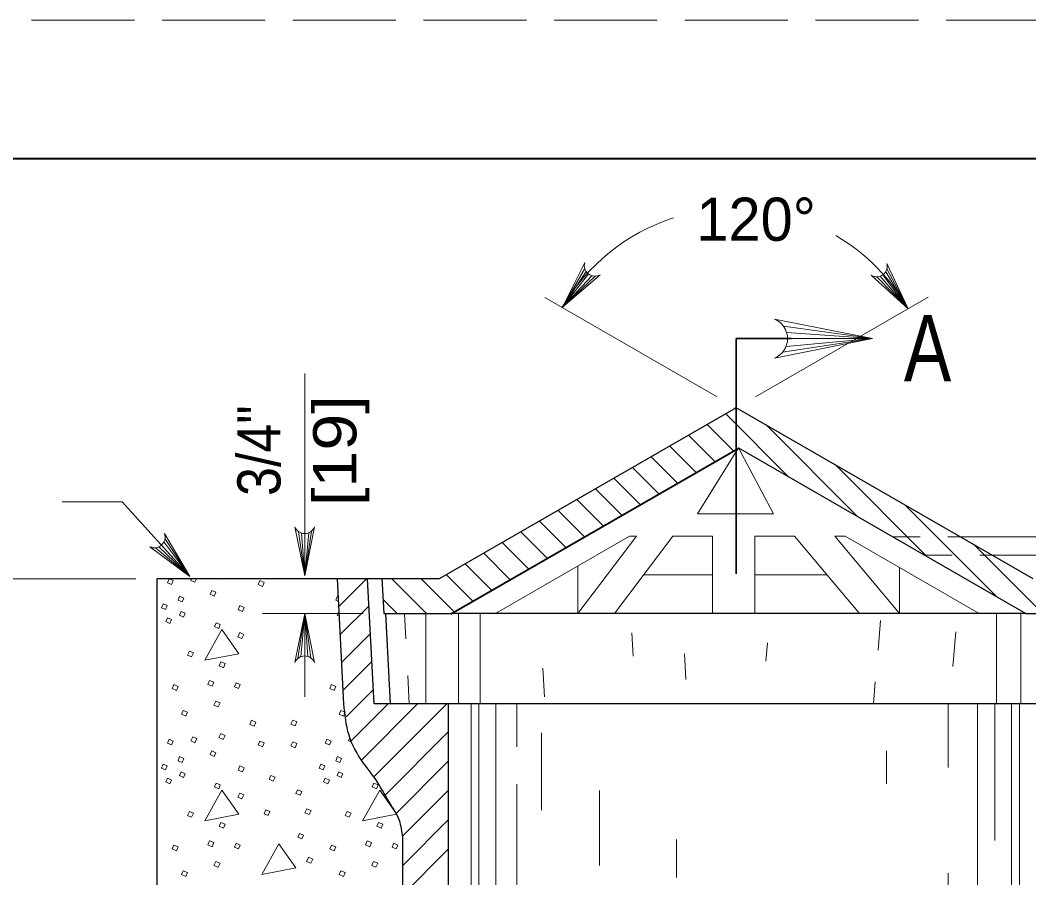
# Model space of a CAD drawing. Extents: x 1036.7 to 1070.7, y 883.9 to 905.9.
# Drawn here: x 1045.244 to 1048.888, y 902.809 to 905.908 of the extents above; entities that cross this region are included whole.
import ezdxf
from ezdxf.enums import TextEntityAlignment as Align

# ---------------------------------------------------------------- set-up
doc = ezdxf.new("R2010")
doc.units = 0
doc.header["$LTSCALE"] = 0.062
doc.linetypes.add('LONG_DASHED', pattern=[7.5, 6, -1.5])
doc.linetypes.add('SHORT_DASHED', pattern=[2.7, 1.5, -1.2])
doc.layers.add('1', color=7, linetype='Continuous', lineweight=13)

msp = doc.modelspace()

# ---------------------------------------------------------------- linework, layer by layer
at = {"layer": '1', "lineweight": 25}
for p, q in [((1038.67333, 905.40825), (1070.17333, 905.40825)), ((1047.83108, 904.5075), (1046.75733, 903.88892)), ((1048.90392, 903.88892), (1047.83108, 904.5075)), ((1046.8015, 903.7615), (1047.8405, 904.36)), ((1046.41367, 903.43767), (1046.38992, 903.88892)), ((1046.5505, 903.88892), (1046.38992, 903.88892)), ((1046.5505, 903.89158), (1046.55725, 903.76383)), ((1046.75733, 903.88892), (1046.5505, 903.88892)), ((1046.55733, 903.76383), (1046.80025, 903.76383)), ((1046.58208, 903.43767), (1046.56483, 903.76383)), ((1048.87742, 903.76383), (1046.80025, 903.76383)), ((1048.89925, 903.43767), (1046.7915, 903.43767)), ((1048.93683, 903.43767), (1046.7915, 903.43767)), ((1046.62592, 900.59025), (1046.62592, 902.95508))]:
    msp.add_line(p, q, dxfattribs=at)
at = {"layer": '1'}
for p, q in [((1047.28333, 905.01067), (1047.20258, 904.8705)), ((1048.37533, 905.01017), (1048.45192, 904.86517)), ((1047.28875, 904.99958), (1047.20258, 904.8705)), ((1047.29667, 904.99133), (1047.20258, 904.8705)), ((1047.30975, 904.98475), (1047.20258, 904.8705)), ((1047.32175, 904.98317), (1047.20258, 904.8705)), ((1048.3385, 904.98058), (1048.45192, 904.86517)), ((1048.35067, 904.98283), (1048.45192, 904.86517)), ((1048.36075, 904.98825), (1048.45192, 904.86517)), ((1048.37067, 904.99908), (1048.45192, 904.86517)), ((1047.76183, 904.54742), (1047.13992, 904.90608)), ((1048.52417, 904.90675), (1047.90033, 904.54742)), ((1048.00208, 904.80225), (1048.32258, 904.75742)), ((1047.99825, 904.70783), (1048.32258, 904.75742)), ((1048.01058, 904.72858), (1048.32258, 904.75742)), ((1048.01292, 904.78008), (1048.32258, 904.75742)), ((1048.01625, 904.75742), (1048.32258, 904.75742)), ((1046.27183, 904.63175), (1046.27183, 903.89992)), ((1047.83108, 904.5075), (1047.82567, 904.50742)), ((1047.79275, 904.4855), (1048.02, 904.25808)), ((1047.7255, 904.44667), (1047.82058, 904.35158)), ((1047.93867, 904.4455), (1048.2705, 904.11375)), ((1047.65817, 904.40792), (1047.75333, 904.31283)), ((1046.80025, 903.76383), (1047.83925, 904.36233)), ((1047.591, 904.36917), (1047.686, 904.27408)), ((1047.69058, 904.12417), (1047.83925, 904.36233)), ((1047.96542, 904.12417), (1047.83925, 904.36233)), ((1047.52367, 904.33042), (1047.61883, 904.23533)), ((1047.4565, 904.29167), (1047.5515, 904.19667)), ((1048.18908, 904.30108), (1048.521, 903.96933)), ((1047.38917, 904.25292), (1047.48425, 904.15783)), ((1047.32192, 904.21417), (1047.417, 904.11908)), ((1045.39583, 904.16733), (1045.613, 904.16733)), ((1045.85717, 903.8975), (1045.613, 904.16733)), ((1047.25467, 904.17542), (1047.34975, 904.08033)), ((1047.18742, 904.13667), (1047.2825, 904.04158)), ((1048.43958, 904.15667), (1048.77133, 903.82492)), ((1047.12008, 904.09792), (1047.21525, 904.00283)), ((1047.69058, 904.12417), (1047.96542, 904.12417)), ((1046.24942, 904.06017), (1046.27183, 903.89992)), ((1046.29667, 904.062), (1046.27183, 903.89992)), ((1047.05292, 904.05925), (1047.14792, 903.96408)), ((1045.76358, 904.02308), (1045.85717, 903.8975)), ((1045.76717, 904.03458), (1045.85717, 903.8975)), ((1046.2605, 904.05467), (1046.27183, 903.89992)), ((1046.28625, 904.05592), (1046.27183, 903.89992)), ((1046.27183, 904.05308), (1046.27183, 903.89992)), ((1046.96075, 903.76383), (1047.44525, 904.04292)), ((1047.47025, 904.04292), (1047.25917, 903.76383)), ((1047.602, 904.04292), (1047.39083, 903.76383)), ((1047.47025, 904.04292), (1047.44525, 904.04292)), ((1047.602, 904.04292), (1047.74542, 904.04292)), ((1047.74542, 904.04292), (1047.74542, 903.76383)), ((1047.89833, 904.04292), (1047.89833, 903.76383)), ((1047.89833, 904.04292), (1048.04175, 904.04292)), ((1048.04175, 904.04292), (1048.27575, 903.76383)), ((1048.18642, 904.04292), (1048.42042, 903.76383)), ((1048.22492, 904.04292), (1048.18642, 904.04292)), ((1048.22492, 904.04292), (1048.70892, 903.76383)), ((1048.63925, 904.04158), (1049.42942, 904.04158)), ((1045.73333, 904.00158), (1045.85717, 903.8975)), ((1045.74525, 904.005), (1045.85717, 903.8975)), ((1045.75475, 904.01133), (1045.85717, 903.8975)), ((1046.98558, 904.02042), (1047.08075, 903.92533)), ((1048.69008, 904.01225), (1048.9385, 903.76383)), ((1046.91842, 903.98167), (1047.01342, 903.88658)), ((1048.75433, 903.97517), (1049.42983, 903.97517)), ((1046.85108, 903.94292), (1046.94617, 903.84783)), ((1047.25917, 903.76383), (1047.25917, 903.93567)), ((1048.42042, 903.76383), (1048.42042, 903.93017)), ((1043.7755, 903.88892), (1045.66242, 903.88892)), ((1046.39517, 903.78892), (1046.49508, 903.88892)), ((1046.587, 903.88892), (1046.71217, 903.76383)), ((1046.69308, 903.88892), (1046.81167, 903.77042)), ((1046.78375, 903.90417), (1046.87892, 903.80908)), ((1047.74542, 903.90342), (1047.49642, 903.90342)), ((1048.15875, 903.90342), (1047.89833, 903.90342)), ((1046.38992, 903.82667), (1046.39325, 903.82508)), ((1046.5545, 903.81542), (1046.60617, 903.76383)), ((1046.39492, 903.77175), (1046.39617, 903.77117)), ((1046.4005, 903.68825), (1046.50417, 903.792)), ((1046.48317, 903.76383), (1046.11925, 903.76383)), ((1046.24708, 903.60167), (1046.27183, 903.76383)), ((1046.2575, 903.60783), (1046.27183, 903.76383)), ((1046.27183, 903.76383), (1046.27183, 903.46283)), ((1046.27183, 903.61067), (1046.27183, 903.76383)), ((1046.28317, 903.609), (1046.27183, 903.76383)), ((1046.29425, 903.60358), (1046.27183, 903.76383)), ((1046.6375, 903.67225), (1046.63267, 903.76383)), ((1046.70942, 903.76383), (1046.70942, 903.43767)), ((1046.82775, 903.76383), (1046.82775, 903.43767)), ((1046.906, 903.76383), (1046.906, 903.43767)), ((1048.35225, 903.739), (1048.343, 903.6315)), ((1048.77117, 903.76383), (1048.77117, 903.43767)), ((1048.85917, 903.76383), (1048.85917, 903.43767)), ((1047.45867, 903.61), (1047.45425, 903.69383)), ((1048.624, 903.69817), (1048.61308, 903.57258)), ((1046.40575, 903.58758), (1046.5095, 903.69133)), ((1047.94392, 903.65817), (1047.93808, 903.59117)), ((1046.41108, 903.48683), (1046.51483, 903.59067)), ((1047.64883, 903.52492), (1047.644, 903.61775)), ((1047.13783, 903.46342), (1047.13242, 903.566)), ((1046.64983, 903.43767), (1046.64442, 903.54025)), ((1048.33317, 903.51725), (1048.32625, 903.43767)), ((1046.42125, 903.391), (1046.52017, 903.48992)), ((1046.43825, 903.30208), (1046.57392, 903.43767)), ((1046.47667, 903.23442), (1046.67992, 903.43767)), ((1046.52167, 903.1735), (1046.78592, 903.43767)), ((1046.7915, 901.57142), (1046.7915, 903.43767)), ((1046.87358, 903.43767), (1046.87358, 900.57858)), ((1046.90042, 903.43767), (1046.90042, 900.57542)), ((1046.96217, 903.43767), (1046.96217, 902.6615)), ((1047.03817, 903.43767), (1047.03817, 903.28183)), ((1048.596, 903.43767), (1048.596, 903.20792)), ((1048.70292, 903.43767), (1048.70292, 902.60083)), ((1048.76475, 903.43767), (1048.76475, 902.94342)), ((1048.8255, 903.43767), (1048.8255, 900.58175)), ((1048.85392, 903.43767), (1048.85392, 900.58933)), ((1046.56217, 903.10783), (1046.7915, 903.33725)), ((1047.12775, 903.33333), (1047.12775, 903.05308)), ((1048.37333, 903.268), (1048.37333, 903.14783)), ((1046.60292, 903.04275), (1046.7915, 903.23125)), ((1047.03817, 903.1475), (1047.03817, 902.67008)), ((1046.60317, 903.04), (1046.54283, 903.12608)), ((1046.62517, 902.95892), (1046.7915, 903.12525)), ((1047.33633, 903.12458), (1047.33633, 902.85308)), ((1046.62592, 902.85367), (1046.7915, 903.01925)), ((1047.615, 902.94733), (1047.615, 902.81017)), ((1046.62592, 902.74767), (1046.7915, 902.91317)), ((1048.596, 902.82617), (1048.596, 902.177))]:
    msp.add_line(p, q, dxfattribs=at)
at = {"layer": '1', "linetype": 'SHORT_DASHED'}
for p, q in [((1048.39567, 904.04158), (1048.63925, 904.04158)), ((1048.51083, 903.97517), (1048.75433, 903.97517))]:
    msp.add_line(p, q, dxfattribs=at)
at = {"layer": '1', "linetype": 'LONG_DASHED'}
msp.add_lwpolyline([(1036.67333, 883.90825), (1070.67333, 883.90825), (1070.67333, 905.90825), (1036.67333, 905.90825)], close=True, dxfattribs=at)
at = {"layer": '1', "lineweight": 40}
msp.add_lwpolyline([(1038.67333, 905.40825), (1070.17333, 905.40825), (1070.17333, 884.40825), (1038.67333, 884.40825)], close=True, dxfattribs=at)
msp.add_lwpolyline([(1038.67333, 905.40825), (1070.17333, 905.40825), (1070.17333, 884.40825), (1038.67333, 884.40825)], close=True, dxfattribs=at)
at = {"layer": '1'}
for points in [[(1047.33925, 904.98842), (1047.20258, 904.8705), (1047.28342, 905.03192)], [(1048.375, 905.0285), (1048.45192, 904.86517), (1048.31808, 904.98633)], [(1047.96858, 904.68658), (1048.32258, 904.75742), (1047.96858, 904.82817)], [(1046.30725, 904.07692), (1046.27183, 903.89992), (1046.23642, 904.07692)], [(1045.76508, 904.05275), (1045.85717, 903.8975), (1045.7125, 904.00533)], [(1045.78375, 903.88892), (1045.79717, 903.88267), (1045.79117, 903.86867), (1045.77617, 903.87467), (1045.78183, 903.88892)], [(1045.88083, 903.88892), (1045.87508, 903.87667), (1045.86017, 903.88367), (1045.86283, 903.88892)], [(1045.97725, 903.88892), (1045.97708, 903.88867), (1045.97658, 903.88892)], [(1046.39425, 903.80758), (1046.38392, 903.81167), (1046.38992, 903.82667)], [(1046.39708, 903.75392), (1046.38892, 903.75775), (1046.39492, 903.77175)], [(1046.23642, 903.58683), (1046.27183, 903.76383), (1046.30725, 903.58683)], [(1046.44183, 903.29842), (1046.42983, 903.304), (1046.43542, 903.31525)], [(1046.54283, 903.12608), (1046.48083, 903.01517), (1046.60358, 903.03917)]]:
    msp.add_lwpolyline(points, dxfattribs=at)
at = {"layer": '1', "lineweight": 35}
msp.add_lwpolyline([(1047.83108, 903.90792), (1047.83108, 904.75742), (1048.031, 904.75742)], dxfattribs=at)
at = {"layer": '1', "lineweight": 25}
for points in [[(1047.83925, 904.36233), (1048.87742, 903.76383), (1049.10158, 903.76383)], [(1046.38992, 903.88892), (1045.73742, 903.88892), (1045.73742, 900.57758)], [(1046.7915, 900.58833), (1046.7915, 903.43767), (1046.52292, 903.43767), (1046.49908, 903.88892)]]:
    msp.add_lwpolyline(points, dxfattribs=at)
at = {"layer": '1'}
for points in [[(1046.11, 903.88267), (1046.125, 903.87567), (1046.119, 903.86167), (1046.104, 903.86867)], [(1045.93608, 903.84767), (1045.95108, 903.84067), (1045.94508, 903.82667), (1045.93008, 903.83367)], [(1045.82017, 903.82667), (1045.83517, 903.81967), (1045.82917, 903.80567), (1045.81417, 903.81167)], [(1045.76017, 903.79867), (1045.77517, 903.79267), (1045.76917, 903.77867), (1045.75417, 903.78467)], [(1045.82517, 903.77175), (1045.84017, 903.76475), (1045.83417, 903.75075), (1045.81917, 903.75775)], [(1046.03808, 903.79267), (1046.053, 903.78567), (1046.04708, 903.77175), (1046.03208, 903.77767)], [(1045.77617, 903.74875), (1045.79117, 903.74175), (1045.78517, 903.72775), (1045.77017, 903.73475)], [(1045.95208, 903.73075), (1045.96708, 903.72475), (1045.96108, 903.70975), (1045.94608, 903.71675)], [(1045.97308, 903.70575), (1045.91108, 903.59483), (1046.03408, 903.61883)], [(1046.03708, 903.69475), (1046.052, 903.68775), (1046.04508, 903.67375), (1046.03008, 903.67975)], [(1045.85517, 903.62783), (1045.87017, 903.62183), (1045.86317, 903.60783), (1045.84817, 903.61383)], [(1045.96908, 903.58883), (1045.98408, 903.58283), (1045.97808, 903.56783), (1045.96308, 903.57483)], [(1045.92808, 903.52183), (1045.94308, 903.51583), (1045.93708, 903.50083), (1045.92208, 903.50783)], [(1046.02408, 903.51383), (1046.03908, 903.50683), (1046.03308, 903.49283), (1046.01808, 903.49883)], [(1045.79917, 903.50683), (1045.81417, 903.49983), (1045.80817, 903.48583), (1045.79317, 903.49283)], [(1046.36892, 903.50683), (1046.38392, 903.49983), (1046.37792, 903.48583), (1046.36292, 903.49283)], [(1045.95108, 903.44692), (1045.96608, 903.44092), (1045.95908, 903.42692), (1045.94408, 903.43292)], [(1045.83317, 903.41392), (1045.84817, 903.40792), (1045.84217, 903.39292), (1045.82717, 903.39992)], [(1046.40283, 903.41392), (1046.41783, 903.40792), (1046.41183, 903.39292), (1046.39692, 903.39992)], [(1046.08, 903.37792), (1046.095, 903.37092), (1046.089, 903.35692), (1046.074, 903.36292)], [(1046.229, 903.37792), (1046.24392, 903.37192), (1046.23692, 903.35792), (1046.222, 903.36392)], [(1045.96908, 903.33), (1045.98408, 903.323), (1045.97708, 903.309), (1045.96208, 903.316)], [(1045.78217, 903.31), (1045.79717, 903.303), (1045.79117, 903.289), (1045.77617, 903.295)], [(1045.86717, 903.318), (1045.88208, 903.312), (1045.87508, 903.297), (1045.86017, 903.304)], [(1046.11, 903.303), (1046.125, 903.296), (1046.119, 903.282), (1046.104, 903.289)], [(1046.229, 903.3), (1046.24392, 903.294), (1046.23692, 903.279), (1046.222, 903.286)], [(1046.35192, 903.31), (1046.36692, 903.303), (1046.36092, 903.289), (1046.34592, 903.295)], [(1045.93608, 903.268), (1045.95108, 903.261), (1045.94508, 903.247), (1045.93008, 903.254)], [(1045.82017, 903.247), (1045.83517, 903.24), (1045.82917, 903.226), (1045.81417, 903.232)], [(1046.38992, 903.247), (1046.40492, 903.24), (1046.39892, 903.226), (1046.38392, 903.232)], [(1045.76017, 903.219), (1045.77517, 903.213), (1045.76917, 903.199), (1045.75417, 903.205)], [(1045.82517, 903.192), (1045.84017, 903.18508), (1045.83417, 903.17108), (1045.81917, 903.17808)], [(1046.03808, 903.213), (1046.053, 903.206), (1046.04708, 903.192), (1046.03208, 903.198)], [(1046.32992, 903.219), (1046.34492, 903.213), (1046.33892, 903.199), (1046.32392, 903.205)], [(1046.39492, 903.192), (1046.40983, 903.18508), (1046.40383, 903.17108), (1046.38892, 903.17808)], [(1045.77617, 903.16908), (1045.79117, 903.16208), (1045.78517, 903.14808), (1045.77017, 903.15508)], [(1045.95208, 903.15108), (1045.96708, 903.14508), (1045.96108, 903.13008), (1045.94608, 903.13708)], [(1046.15, 903.17908), (1046.165, 903.17308), (1046.158, 903.15808), (1046.143, 903.16508)], [(1046.34592, 903.16908), (1046.36092, 903.16208), (1046.35492, 903.14808), (1046.33992, 903.15508)], [(1046.52183, 903.15108), (1046.53683, 903.14508), (1046.53083, 903.13008), (1046.51583, 903.13708)], [(1045.97308, 903.12608), (1045.91108, 903.01517), (1046.03408, 903.03917)], [(1046.03708, 903.11508), (1046.052, 903.10808), (1046.04508, 903.09408), (1046.03008, 903.10008)], [(1046.24592, 903.12708), (1046.26092, 903.12108), (1046.25492, 903.10708), (1046.23992, 903.11308)], [(1045.85517, 903.04808), (1045.87017, 903.04217), (1045.86317, 903.02817), (1045.84817, 903.03417)], [(1046.131, 903.05408), (1046.146, 903.04808), (1046.14, 903.03417), (1046.125, 903.04017)], [(1046.27992, 903.05808), (1046.29492, 903.05208), (1046.28792, 903.03817), (1046.27292, 903.04417)], [(1046.42483, 903.04808), (1046.43983, 903.04217), (1046.43283, 903.02817), (1046.41783, 903.03417)], [(1045.96908, 903.00917), (1045.98408, 903.00317), (1045.97808, 902.98817), (1045.96308, 902.99517)], [(1046.53883, 903.00917), (1046.55383, 903.00317), (1046.54783, 902.98817), (1046.53283, 902.99517)], [(1046.25292, 902.96917), (1046.26792, 902.96317), (1046.26192, 902.94917), (1046.24692, 902.95517)], [(1045.92808, 902.94217), (1045.94308, 902.93617), (1045.93708, 902.92117), (1045.92208, 902.92817)], [(1046.02408, 902.93417), (1046.03908, 902.92717), (1046.03308, 902.91317), (1046.01808, 902.91917)], [(1046.179, 902.93217), (1046.117, 902.82125), (1046.23992, 902.84525)], [(1046.49783, 902.94217), (1046.51283, 902.93617), (1046.50683, 902.92117), (1046.49183, 902.92817)], [(1046.59375, 902.93417), (1046.60875, 902.92717), (1046.60275, 902.91317), (1046.58775, 902.91917)], [(1045.79917, 902.92717), (1045.81417, 902.92017), (1045.80817, 902.90617), (1045.79317, 902.91317)], [(1046.36892, 902.92717), (1046.38392, 902.92017), (1046.37792, 902.90617), (1046.36292, 902.91317)], [(1045.95108, 902.86725), (1045.96608, 902.86125), (1045.95908, 902.84725), (1045.94408, 902.85325)], [(1046.28592, 902.88325), (1046.30092, 902.87625), (1046.29392, 902.86225), (1046.27892, 902.86825)], [(1046.52083, 902.86725), (1046.53583, 902.86125), (1046.52883, 902.84725), (1046.51383, 902.85325)], [(1045.83317, 902.83425), (1045.84817, 902.82825), (1045.84217, 902.81325), (1045.82717, 902.82025)], [(1046.40283, 902.83425), (1046.41783, 902.82825), (1046.41183, 902.81325), (1046.39692, 902.82025)]]:
    msp.add_lwpolyline(points, close=True, dxfattribs=at)
for centre, radius, start, end in [((1047.82571, 904.50745), 0.72117, 107.92241, 149.77549), ((1047.82571, 904.50745), 0.72117, 29.73682, 59.63186), ((1047.32007, 905.02144), 0.0382, 164.18133, 300.00746), ((1048.33802, 905.01886), 0.0382, 238.6148, 14.44092), ((1047.93996, 904.75747), 0.0764, 292.08605, 67.91218), ((1046.27182, 904.09118), 0.0382, 202.08782, 337.91395), ((1045.72921, 904.03964), 0.0382, 244.07291, 19.89904), ((1046.27189, 903.5725), 0.0382, 22.08782, 157.91395)]:
    msp.add_arc(centre, radius, start, end, dxfattribs=at)
at = {"layer": '1', "lineweight": 25}
msp.add_spline([(1046.62592, 902.95508), (1046.61417, 903.01567), (1046.57658, 903.08325), (1046.52842, 903.16425), (1046.482, 903.2265), (1046.43208, 903.324), (1046.41367, 903.43767)], degree=3, dxfattribs=at)

# ---------------------------------------------------------------- texts
at = {"layer": '1'}
msp.add_text('120°', height=0.156, dxfattribs=at).set_placement((1047.68683, 905.11092))
at = {"layer": '1', "width": 0.8}
msp.add_text('A', height=0.24, dxfattribs=at).set_placement((1048.43633, 904.60267))
at = {"layer": '1'}
for s, width, p in [('[19]', 1.15, (1046.45842, 904.35254)), ('3/4"', 0.9, (1046.18442, 904.35258))]:
    msp.add_text(s, height=0.156, rotation=90, dxfattribs=dict(at, width=width)).set_placement(p, align=Align.CENTER)

doc.saveas('drawing.dxf')
